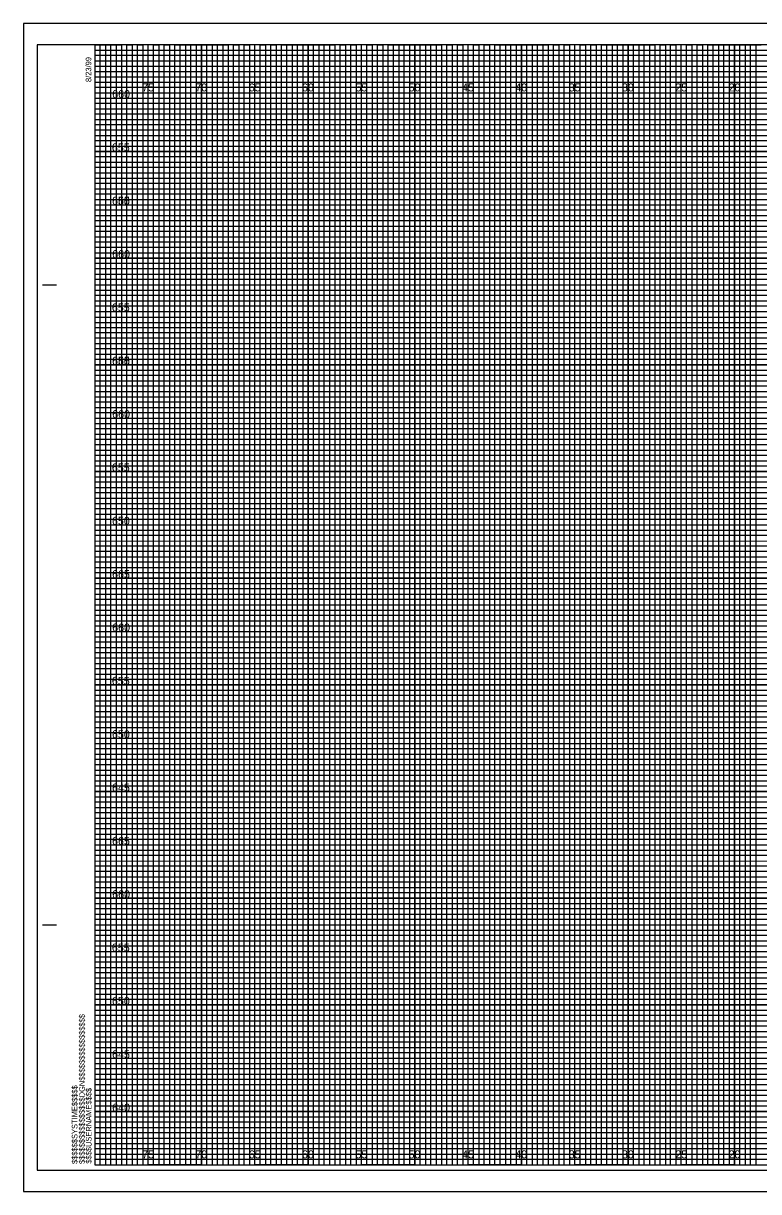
# Model space of a CAD drawing. Extents: x -7 to 162, y 548 to 657.
# Drawn here: x -6.7 to 62.2, y 547.5 to 657 of the extents above; entities that cross this region are included whole.
import ezdxf

# ---------------------------------------------------------------- set-up
doc = ezdxf.new("R2010")
doc.units = 0
for name, color, linetype in [('Exist Cross Section Cell', 7, 'Continuous'), ('Exist XS Center Line Elevation Label', 7, 'Continuous'), ('Exist XS Ground Line', 7, 'Continuous'), ('Prop CMT Pvmt Course 1 Wedge', 7, 'Continuous'), ('Prop CMT Pvmt Course 2 Wedge', 7, 'Continuous'), ('Prop CMT Pvmt Surface', 7, 'Continuous'), ('Prop CMT Shld Paved Course 1', 7, 'Continuous'), ('Prop CMT Shld Paved Course 2', 7, 'Continuous'), ('Prop CMT Shld Paved Course 3', 7, 'Continuous'), ('Prop CMT Slope Grass', 7, 'Continuous'), ('Prop XS EOT Tick Mark', 7, 'Continuous')]:
    doc.layers.add(name, color=color, linetype=linetype)

msp = doc.modelspace()

# ---------------------------------------------------------------- linework, layer by layer
at = {"layer": 'Exist XS Center Line Elevation Label'}
for points in [[(0, 655), (2.5, 655), (2.5, 550), (7.5, 550), (7.5, 655), (12.5, 655), (12.5, 550), (17.5, 550), (17.5, 655), (22.5, 655), (22.5, 550), (27.5, 550), (27.5, 655), (32.5, 655), (32.5, 550), (37.5, 550), (37.5, 655), (42.5, 655), (42.5, 550), (47.5, 550), (47.5, 655), (52.5, 655), (52.5, 550), (57.5, 550), (57.5, 655), (62.5, 655)], [(0, 652.5), (137.5, 652.5)], [(0, 642.5), (160, 642.5), (160, 647.5), (0, 647.5)], [(0, 632.5), (160, 632.5), (160, 637.5), (0, 637.5)], [(0, 622.5), (160, 622.5), (160, 627.5), (0, 627.5)], [(0, 612.5), (160, 612.5), (160, 617.5), (0, 617.5)], [(0, 602.5), (160, 602.5), (160, 607.5), (0, 607.5)], [(0, 592.5), (160, 592.5), (160, 597.5), (0, 597.5)], [(0, 582.5), (160, 582.5), (160, 587.5), (0, 587.5)], [(0, 572.5), (160, 572.5), (160, 577.5), (0, 577.5)], [(0, 562.5), (160, 562.5), (160, 567.5), (0, 567.5)], [(0, 552.5), (160, 552.5), (160, 557.5), (0, 557.5)]]:
    msp.add_lwpolyline(points, dxfattribs=at)
at = {"layer": 'Exist XS Ground Line'}
for p, q in [((5, 655), (0, 655)), ((5, 550), (5, 655)), ((15, 655), (10, 655)), ((10, 655), (10, 550)), ((15, 550), (15, 655)), ((25, 655), (20, 655)), ((20, 655), (20, 550)), ((25, 550), (25, 655)), ((35, 655), (30, 655)), ((30, 655), (30, 550)), ((35, 550), (35, 655)), ((45, 655), (40, 655)), ((40, 655), (40, 550)), ((45, 550), (45, 655)), ((55, 655), (50, 655)), ((50, 655), (50, 550)), ((55, 550), (55, 655)), ((65, 655), (60, 655)), ((60, 655), (60, 550)), ((10, 550), (5, 550)), ((20, 550), (15, 550)), ((30, 550), (25, 550)), ((40, 550), (35, 550)), ((50, 550), (45, 550)), ((60, 550), (55, 550))]:
    msp.add_line(p, q, dxfattribs=at)
for points in [[(0, 650), (160, 650), (160, 645), (0, 645)], [(0, 640), (160, 640), (160, 635), (0, 635)], [(0, 630), (160, 630), (160, 625), (0, 625)], [(0, 620), (160, 620), (160, 615), (0, 615)], [(0, 610), (160, 610), (160, 605), (0, 605)], [(0, 600), (160, 600), (160, 595), (0, 595)], [(0, 590), (160, 590), (160, 585), (0, 585)], [(0, 580), (160, 580), (160, 575), (0, 575)], [(0, 570), (160, 570), (160, 565), (0, 565)], [(0, 560), (160, 560), (160, 555), (0, 555)]]:
    msp.add_lwpolyline(points, dxfattribs=at)
at = {"layer": 'Prop CMT Pvmt Course 1 Wedge'}
for p, q in [((161.65, 657), (-6.7, 657)), ((-6.7, 657), (-6.7, 547.5)), ((-6.7, 547.5), (161.65, 547.5))]:
    msp.add_line(p, q, dxfattribs=at)
at = {"layer": 'Prop CMT Pvmt Surface'}
for points in [[(0, 550), (0.5, 550), (0.5, 655), (1, 655), (1, 550)], [(1, 550), (1.5, 550), (1.5, 655), (2, 655), (2, 550)], [(2.5, 550), (3, 550), (3, 655), (3.5, 655), (3.5, 550)], [(3.5, 550), (4, 550), (4, 655), (4.5, 655), (4.5, 550)], [(5, 550), (5.5, 550), (5.5, 655), (6, 655), (6, 550)], [(6, 550), (6.5, 550), (6.5, 655), (7, 655), (7, 550)], [(7.5, 550), (8, 550), (8, 655), (8.5, 655), (8.5, 550)], [(8.5, 550), (9, 550), (9, 655), (9.5, 655), (9.5, 550)], [(10, 550), (10.5, 550), (10.5, 655), (11, 655), (11, 550)], [(11, 550), (11.5, 550), (11.5, 655), (12, 655), (12, 550)], [(12.5, 550), (13, 550), (13, 655), (13.5, 655), (13.5, 550)], [(13.5, 550), (14, 550), (14, 655), (14.5, 655), (14.5, 550)], [(15, 550), (15.5, 550), (15.5, 655), (16, 655), (16, 550)], [(16, 550), (16.5, 550), (16.5, 655), (17, 655), (17, 550)], [(17.5, 550), (18, 550), (18, 655), (18.5, 655), (18.5, 550)], [(18.5, 550), (19, 550), (19, 655), (19.5, 655), (19.5, 550)], [(20, 550), (20.5, 550), (20.5, 655), (21, 655), (21, 550)], [(21, 550), (21.5, 550), (21.5, 655), (22, 655), (22, 550)], [(22.5, 550), (23, 550), (23, 655), (23.5, 655), (23.5, 550)], [(23.5, 550), (24, 550), (24, 655), (24.5, 655), (24.5, 550)], [(25, 550), (25.5, 550), (25.5, 655), (26, 655), (26, 550)], [(26, 550), (26.5, 550), (26.5, 655), (27, 655), (27, 550)], [(27.5, 550), (28, 550), (28, 655), (28.5, 655), (28.5, 550)], [(28.5, 550), (29, 550), (29, 655), (29.5, 655), (29.5, 550)], [(30, 550), (30.5, 550), (30.5, 655), (31, 655), (31, 550)], [(31, 550), (31.5, 550), (31.5, 655), (32, 655), (32, 550)], [(32.5, 550), (33, 550), (33, 655), (33.5, 655), (33.5, 550)], [(33.5, 550), (34, 550), (34, 655), (34.5, 655), (34.5, 550)], [(35, 550), (35.5, 550), (35.5, 655), (36, 655), (36, 550)], [(36, 550), (36.5, 550), (36.5, 655), (37, 655), (37, 550)], [(37.5, 550), (38, 550), (38, 655), (38.5, 655), (38.5, 550)], [(38.5, 550), (39, 550), (39, 655), (39.5, 655), (39.5, 550)], [(40, 550), (40.5, 550), (40.5, 655), (41, 655), (41, 550)], [(41, 550), (41.5, 550), (41.5, 655), (42, 655), (42, 550)], [(42.5, 550), (43, 550), (43, 655), (43.5, 655), (43.5, 550)], [(43.5, 550), (44, 550), (44, 655), (44.5, 655), (44.5, 550)], [(45, 550), (45.5, 550), (45.5, 655), (46, 655), (46, 550)], [(46, 550), (46.5, 550), (46.5, 655), (47, 655), (47, 550)], [(47.5, 550), (48, 550), (48, 655), (48.5, 655), (48.5, 550)], [(48.5, 550), (49, 550), (49, 655), (49.5, 655), (49.5, 550)], [(50, 550), (50.5, 550), (50.5, 655), (51, 655), (51, 550)], [(51, 550), (51.5, 550), (51.5, 655), (52, 655), (52, 550)], [(52.5, 550), (53, 550), (53, 655), (53.5, 655), (53.5, 550)], [(53.5, 550), (54, 550), (54, 655), (54.5, 655), (54.5, 550)], [(55, 550), (55.5, 550), (55.5, 655), (56, 655), (56, 550)], [(56, 550), (56.5, 550), (56.5, 655), (57, 655), (57, 550)], [(57.5, 550), (58, 550), (58, 655), (58.5, 655), (58.5, 550)], [(58.5, 550), (59, 550), (59, 655), (59.5, 655), (59.5, 550)], [(60, 550), (60.5, 550), (60.5, 655), (61, 655), (61, 550)], [(61, 550), (61.5, 550), (61.5, 655), (62, 655), (62, 550)]]:
    msp.add_lwpolyline(points, dxfattribs=at)
at = {"layer": 'Prop CMT Shld Paved Course 1'}
msp.add_lwpolyline([(-6.7, 547.5), (161.65, 547.5), (161.65, 657), (-6.7, 657)], close=True, dxfattribs=at)
at = {"layer": 'Prop CMT Shld Paved Course 2'}
msp.add_lwpolyline([(-5.4, 549.5), (161.2, 549.5), (161.2, 655), (-5.4, 655)], close=True, dxfattribs=at)
at = {"layer": 'Prop CMT Shld Paved Course 3'}
for p, q in [((5, 550), (5, 655)), ((10, 550), (10, 655)), ((15, 550), (15, 655)), ((20, 550), (20, 655)), ((25, 550), (25, 655)), ((30, 550), (30, 655)), ((35, 550), (35, 655)), ((40, 550), (40, 655)), ((45, 550), (45, 655)), ((50, 550), (50, 655)), ((55, 550), (55, 655)), ((60, 550), (60, 655)), ((0, 650), (160, 650)), ((0, 645), (160, 645)), ((0, 640), (160, 640)), ((0, 635), (160, 635)), ((0, 630), (160, 630)), ((0, 625), (160, 625)), ((0, 620), (160, 620)), ((0, 615), (160, 615)), ((0, 610), (160, 610)), ((0, 605), (160, 605)), ((0, 600), (160, 600)), ((0, 595), (160, 595)), ((0, 590), (160, 590)), ((0, 585), (160, 585)), ((0, 580), (160, 580)), ((0, 575), (160, 575)), ((0, 570), (160, 570)), ((0, 565), (160, 565)), ((0, 560), (160, 560)), ((0, 555), (160, 555))]:
    msp.add_line(p, q, dxfattribs=at)
at = {"layer": 'Prop CMT Slope Grass'}
for p, q in [((-4.9, 632.5), (-3.65, 632.5)), ((-4.85, 632.5), (-3.6, 632.5)), ((-4.9, 572.5), (-3.65, 572.5)), ((-4.85, 572.5), (-3.6, 572.5)), ((0, 550), (0, 550)), ((0, 550), (0, 550)), ((0, 550), (0, 550)), ((0, 550), (0, 550)), ((0, 550), (0, 550)), ((0, 550), (0, 550)), ((0, 550), (0, 550))]:
    msp.add_line(p, q, dxfattribs=at)
msp.add_lwpolyline([(160, 655), (0, 655), (0, 550), (160, 550)], close=True, dxfattribs=at)
at = {"layer": 'Prop XS EOT Tick Mark'}
for p, q in [((0, 654.5), (130, 654.5)), ((130, 653.99), (0, 653.99)), ((0, 653.99), (0, 653.5)), ((0, 653.5), (130, 653.5)), ((130, 652.95), (0, 652.95)), ((0, 652.95), (0, 652)), ((0, 652), (160, 652))]:
    msp.add_line(p, q, dxfattribs=at)
for points in [[(0, 651.5), (135, 651.5), (160, 651.5), (160, 651), (0, 651)], [(0, 650.5), (160, 650.5), (160, 649.5), (0, 649.5)], [(0, 649), (160, 649), (160, 648.5), (0, 648.49)], [(0, 648), (160, 648), (160, 647), (0, 647)], [(0, 646.5), (160, 646.5), (160, 646), (0, 646)], [(0, 645.5), (160, 645.5), (160, 644.5), (0, 644.5)], [(0, 644), (160, 644), (160, 643.5), (0, 643.5)], [(0, 643), (160, 643), (160, 642), (0, 642)], [(0, 641.5), (160, 641.5), (160, 641), (0, 641)], [(0, 640.5), (160, 640.5), (160, 639.5), (0, 639.5)], [(0, 639), (160, 639), (160, 638.5), (0, 638.5)], [(0, 638), (160, 638), (160, 636.98), (160, 636.5), (160, 636), (0, 636)], [(0, 637), (160, 637), (160, 636.5), (0, 636.5)], [(0, 635.5), (160, 635.5), (160, 634.5), (0, 634.51)], [(0, 634.51), (160, 634.5), (160, 634), (0, 634)], [(0, 633.5), (160, 633.5), (160, 633), (0, 633)], [(0, 632), (160, 632), (160, 631.5), (0, 631.5)], [(0, 631), (160, 631), (160, 630.5), (0, 630.5)], [(-0.04, 629.45), (160, 629.45), (160, 628.94), (-0.04, 628.94)], [(0, 628.5), (160, 628.5), (160, 628), (0, 628)], [(0, 627), (160, 627), (160, 626.5), (0, 626.5)], [(0, 626), (160, 626), (160, 625.5), (0, 625.5)], [(0, 624.5), (160, 624.5), (160, 624), (0, 624)], [(0, 623.5), (160, 623.5), (160, 623), (0, 623)], [(0, 622), (160, 622), (160, 621.5), (0, 621.5)], [(0, 621), (160, 621), (160, 620.5), (0, 620.5)], [(0, 619.5), (160, 619.5), (160, 618.99), (0, 619)], [(0, 618.5), (160, 618.5), (160, 618), (0, 618)], [(0, 617), (160, 617), (160, 616.5), (0, 616.5)], [(0, 616), (160, 616), (160, 615.5), (0, 615.5)], [(0, 614.5), (160, 614.5), (160, 614), (0, 614)], [(0, 613.5), (160, 613.5), (160, 613), (0, 613)], [(0, 612), (160, 612), (160, 611.5), (0, 611.5)], [(0, 611), (160, 611), (160, 610.5), (0, 610.5)], [(0, 609.5), (160, 609.5), (160, 609), (0, 609)], [(0, 608.5), (160.03, 608.46), (160, 608), (0, 608)], [(0, 607), (160, 607), (160, 606.5), (0, 606.5)], [(0, 606), (160, 606), (160, 605.5), (0, 605.5)], [(0, 604.5), (160, 604.5), (160, 604), (0, 604)], [(0, 603.5), (160, 603.5), (160, 603), (0, 603)], [(0, 602), (160, 602), (160, 601.5), (0, 601.5)], [(0, 601), (160, 601), (160, 600.5), (0, 600.5)], [(0, 599.5), (160, 599.5), (160, 599), (0, 599)], [(0, 598.5), (160, 598.5), (160, 598), (0, 598)], [(0, 597), (160, 597), (160, 596.5), (0, 596.5)], [(0, 596), (160, 596), (160, 595.5), (0, 595.5)], [(0, 594.5), (160, 594.5), (160, 594), (0, 594)], [(0, 593.5), (160, 593.5), (160, 593), (0, 593)], [(0, 592), (160, 592), (160, 591.5), (0, 591.5)], [(0, 591), (160, 591), (160, 590.5), (0, 590.5)], [(0, 589.5), (160, 589.5), (160, 588.99), (0, 589)], [(0, 588.5), (160, 588.5), (160, 588), (0, 588)], [(0, 587), (160, 587), (160, 586.5), (0, 586.5)], [(0, 586), (160, 586), (160, 585.5), (0, 585.5)], [(0, 584.5), (160, 584.5), (160, 584), (0, 584)], [(0, 583.5), (160, 583.5), (160, 583), (0, 583)], [(0, 582), (160, 582), (160, 581.5), (0, 581.5)], [(0, 581), (160, 581), (160, 580.5), (0, 580.5)], [(0, 579.5), (160, 579.5), (160, 579), (0, 579)], [(0, 578.5), (160.03, 578.46), (160, 578), (0, 578)], [(0, 577), (160, 577), (160, 576.5), (0, 576.5)], [(0, 576), (160, 576), (160, 575.5), (0, 575.5)], [(0, 574.5), (160, 574.5), (160, 574), (0, 574)], [(0, 573.5), (160, 573.5), (160, 573), (0, 573)], [(0, 572), (160, 572), (160, 571.5), (0, 571.5)], [(0, 571), (160, 571), (160, 570.5), (0, 570.5)], [(0, 569.5), (160, 569.5), (160, 569), (0, 569)], [(0, 568.5), (160, 568.5), (160, 568), (0, 568)], [(0, 567), (160, 567), (160, 566.5), (0, 566.5)], [(0, 566), (160, 566), (160, 565.5), (0, 565.5)], [(0, 564.5), (160, 564.5), (160, 564), (0, 564)], [(0, 563.5), (160, 563.5), (160, 563), (0, 563)], [(0, 562), (160, 562), (160, 561.5), (0, 561.5)], [(0, 561), (160, 561), (160, 560.5), (0, 560.5)], [(0, 559.5), (160, 559.5), (160, 559), (0, 559)], [(0, 558.5), (160, 558.5), (160, 558), (0, 558)], [(0, 557), (160, 557), (160, 556.5), (0, 556.5)], [(0, 556), (160, 556), (160, 555.5), (0, 555.5)], [(0, 554.5), (160, 554.5), (160, 554), (0, 554)], [(0, 553.5), (160, 553.5), (160, 553), (0, 553)], [(0, 552), (160, 552), (160, 551.5), (0, 551.5)], [(0, 551), (160, 551), (160, 550.5), (0, 550.5)]]:
    msp.add_lwpolyline(points, dxfattribs=at)

# ---------------------------------------------------------------- texts
at = {"layer": 'Exist Cross Section Cell'}
for s, p in [('75', (4.44, 650.62)), ('70', (9.43, 650.62)), ('65', (14.44, 650.62)), ('60', (19.43, 650.62)), ('55', (24.44, 650.62)), ('50', (29.43, 650.62)), ('45', (34.44, 650.62)), ('40', (39.43, 650.62)), ('35', (44.44, 650.62)), ('30', (49.43, 650.62)), ('25', (54.44, 650.62)), ('20', (59.43, 650.62)), ('75', (4.44, 550.62)), ('70', (9.43, 550.62)), ('65', (14.44, 550.62)), ('60', (19.43, 550.62)), ('55', (24.44, 550.62)), ('50', (29.43, 550.62)), ('45', (34.44, 550.62)), ('40', (39.43, 550.62)), ('35', (44.44, 550.62)), ('30', (49.43, 550.62)), ('25', (54.44, 550.62)), ('20', (59.43, 550.62))]:
    msp.add_text(s, height=0.75, dxfattribs=at).set_placement(p)
at = {"layer": 'Prop CMT Pvmt Course 2 Wedge'}
for s, p in [('660', (1.63, 650)), ('655', (1.6, 645)), ('650', (1.61, 640)), ('665', (1.62, 640)), ('660', (1.63, 635)), ('655', (1.6, 630)), ('650', (1.61, 625)), ('665', (1.62, 625)), ('660', (1.63, 620)), ('655', (1.6, 615)), ('650', (1.61, 610)), ('665', (1.62, 605)), ('660', (1.63, 600)), ('655', (1.6, 595)), ('650', (1.61, 590)), ('645', (1.62, 585)), ('665', (1.62, 580)), ('660', (1.63, 575)), ('655', (1.6, 570)), ('650', (1.61, 565)), ('645', (1.62, 560)), ('640', (1.63, 555))]:
    msp.add_text(s, height=0.75, dxfattribs=at).set_placement(p)
at = {"layer": 'Prop CMT Slope Grass'}
for s, p in [('8/23/99', (-0.33, 651.5)), ('$$$$$$$$$$$$$$$$DGN$$$$$$$$$$$$$$$$', (-0.94, 550.09)), ('$$$$$$SYSTIME$$$$$', (-1.63, 550.09)), ('$$$$USERNAME$$$$', (-0.31, 550.12))]:
    msp.add_text(s, height=0.525, rotation=90, dxfattribs=at).set_placement(p)

doc.saveas('drawing.dxf')
